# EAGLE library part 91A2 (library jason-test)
91 Series Potentiometer
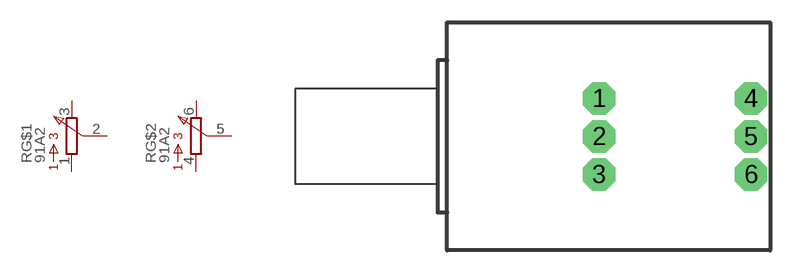
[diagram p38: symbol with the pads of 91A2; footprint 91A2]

Designator prefix R; gates G$1=VR G$2=VR

## 91A2  [91A2]
1  G$1:1  pas
2  G$1:2  pas
3  G$1:3  pas
4  G$2:1  pas
5  G$2:2  pas
6  G$2:3  pas

## Footprint 91A2 (pad centres in mm)
91 Series
drill 1.27 pad 2.184 octagon: 1 0,2.54; 2 0,0; 3 0,-2.54; 4 10.16,2.54; 5 10.16,0; 6 10.16,-2.54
